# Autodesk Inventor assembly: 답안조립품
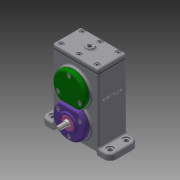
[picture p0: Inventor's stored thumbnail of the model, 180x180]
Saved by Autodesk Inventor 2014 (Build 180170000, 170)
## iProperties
Created: 2020-05
Part Number: 답안조립품
Document SubType Name: Assembly
Designer: kh
Author: kh
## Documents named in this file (24)
- C:\Users\kh\Desktop\600506V1025\답안조립품.iam
- C:\Users\kh\Desktop\600506V1025\본체.ipt
- C:\Users\kh\Desktop\600506V1025\개스킷 A.ipt
- C:\Users\kh\Desktop\600506V1025\개스킷 B.ipt
- C:\Users\kh\Desktop\600506V1025\개스킷 C.ipt
- C:\Users\kh\Desktop\600506V1025\베어링 6001.ipt
- 베어링 6001.ipt
- C:\Users\kh\Desktop\600506V1025\베어링 6002.ipt
- 베어링 6002.ipt
- C:\Users\kh\Desktop\600506V1025\볼트 M4.ipt
- C:\Users\kh\Desktop\600506V1025\스퍼기어 A.ipt
- C:\Users\kh\Desktop\600506V1025\스퍼기어 B.ipt
- C:\Users\kh\Desktop\600506V1025\오일 실 10 20 7.ipt
- C:\Users\kh\Desktop\600506V1025\오일 실 12 22 7.ipt
- C:\Users\kh\Desktop\600506V1025\축 A.ipt
- C:\Users\kh\Desktop\600506V1025\축 B.ipt
- C:\Users\kh\Desktop\600506V1025\칼라.ipt
- C:\Users\kh\Desktop\600506V1025\커버 A.ipt
- C:\Users\kh\Desktop\600506V1025\커버 B.ipt
- C:\Users\kh\Desktop\600506V1025\커버 C.ipt
- C:\Users\kh\Desktop\600506V1025\커버 D.ipt
- C:\Users\kh\Desktop\600506V1025\커버 E.ipt
- C:\Users\kh\Desktop\600506V1025\키 4 x 4 x 12.ipt
- C:\Users\kh\Desktop\600506V1025\키 5 x 5 x 12.ipt
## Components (5 placed, 3 different names)
1. 개스킷 A:1
2. 개스킷 B:1
3. 개스킷 C:1 — 플러쉬:1, 플러쉬:2, 각도:5, 각도:6, 각도:7, 각도:8
4. 개스킷 B:2
5. 개스킷 B:3
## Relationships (6: Angle 4, Flush 2)
- 플러쉬:1 [Flush]: 개스킷 C:1
- 플러쉬:2 [Flush]: 개스킷 C:1
- 각도:5 [Angle]: 개스킷 C:1
- 각도:6 [Angle]: 개스킷 C:1
- 각도:7 [Angle]: 개스킷 C:1
- 각도:8 [Angle]: 개스킷 C:1
